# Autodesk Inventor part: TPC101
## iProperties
Shininess: 64.0
Length Units: 11272
Angle Units: 11279
Time Units: 11290
Mass Units: 11286
Length Display Precision: 3
Angle Display Precision: 2
Compacted: True
Part Number: TPC101
Document SubType Name: Modeling
Created: 2004-08
Designer: Lori
Manufacturer: Standard
Standards Organization: Custom
Density: 0.0
Volumn: 0.0
Area: 0.0
PropertySet Name: Model Information
Control State: 0
Master: False
Checked Out: False
Author: Lori
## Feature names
1. Base1
